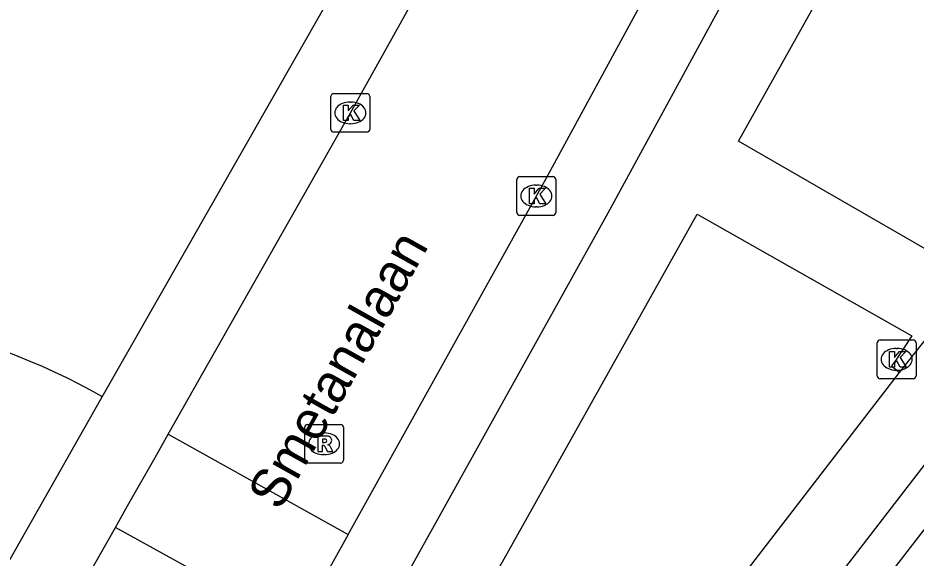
# Model space of a CAD drawing. Extents: x 159040 to 160094, y 381214 to 382518.
# Drawn here: x 159188.7 to 159211.87, y 381534.73 to 381548.68 of the extents above; entities that cross this region are included whole.
import ezdxf

# ---------------------------------------------------------------- set-up
doc = ezdxf.new("R2010")
doc.units = 0
for name, color, linetype in [('IMGEO_Groenvoorziening', 7, 'Continuous'), ('IMGEO_Kolk', 7, 'Continuous'), ('IMGEO_Openbare_ruimte_label', 7, 'Continuous'), ('IMGEO_Pand', 7, 'Continuous'), ('IMGEO_Rijbaan_lokaal_open', 7, 'Continuous'), ('IMGEO_Rioolput', 7, 'Continuous'), ('IMGEO_Voetpad_open', 7, 'Continuous')]:
    doc.layers.add(name, color=color, linetype=linetype)

msp = doc.modelspace()

# ---------------------------------------------------------------- linework, layer by layer
at = {"layer": 'IMGEO_Groenvoorziening'}
msp.add_arc((159182.126, 381523.448), 17.751, 60.4649, 199.9506, dxfattribs=at)
at = {"layer": 'IMGEO_Kolk'}
for p, q in [((159196.775, 381545.799), (159196.775, 381546.651)), ((159196.85, 381546.725), (159197.702, 381546.725)), ((159197.776, 381546.651), (159197.776, 381545.799)), ((159197.263, 381546.505), (159197.288, 381546.505)), ((159197.286, 381545.945), (159197.261, 381545.945)), ((159197.702, 381545.725), (159196.85, 381545.725)), ((159201.574, 381543.652), (159201.574, 381544.504)), ((159201.649, 381544.578), (159202.501, 381544.578)), ((159202.575, 381544.504), (159202.575, 381543.652)), ((159202.062, 381544.358), (159202.087, 381544.358)), ((159202.085, 381543.798), (159202.06, 381543.798)), ((159202.501, 381543.578), (159201.649, 381543.578)), ((159210.945, 381540.36), (159211.797, 381540.36)), ((159210.87, 381539.434), (159210.87, 381540.286)), ((159211.358, 381540.14), (159211.383, 381540.14)), ((159211.871, 381540.286), (159211.871, 381539.434)), ((159211.381, 381539.58), (159211.356, 381539.58)), ((159211.797, 381539.36), (159210.945, 381539.36))]:
    msp.add_line(p, q, dxfattribs=at)
for points in [[(159196.775, 381545.799), (159196.775, 381546.651)], [(159196.85, 381546.725), (159197.702, 381546.725)], [(159197.776, 381546.651), (159197.776, 381545.799)], [(159197.096, 381546.425), (159197.219, 381546.425), (159197.219, 381546.274), (159197.349, 381546.425), (159197.513, 381546.425), (159197.367, 381546.274), (159197.52, 381546.025), (159197.368, 381546.025), (159197.283, 381546.189), (159197.219, 381546.122), (159197.219, 381546.025), (159197.096, 381546.025), (159197.096, 381546.425)], [(159197.702, 381545.725), (159196.85, 381545.725)], [(159201.574, 381543.652), (159201.574, 381544.504)], [(159201.649, 381544.578), (159202.501, 381544.578)], [(159202.575, 381544.504), (159202.575, 381543.652)], [(159201.895, 381544.278), (159202.018, 381544.278), (159202.018, 381544.127), (159202.148, 381544.278), (159202.312, 381544.278), (159202.166, 381544.127), (159202.319, 381543.878), (159202.167, 381543.878), (159202.082, 381544.042), (159202.018, 381543.975), (159202.018, 381543.878), (159201.895, 381543.878), (159201.895, 381544.278)], [(159202.501, 381543.578), (159201.649, 381543.578)], [(159210.945, 381540.36), (159211.797, 381540.36)], [(159210.87, 381539.434), (159210.87, 381540.286)], [(159211.871, 381540.286), (159211.871, 381539.434)], [(159211.191, 381540.06), (159211.314, 381540.06), (159211.314, 381539.909), (159211.444, 381540.06), (159211.608, 381540.06), (159211.462, 381539.909), (159211.615, 381539.66), (159211.463, 381539.66), (159211.378, 381539.824), (159211.314, 381539.757), (159211.314, 381539.66), (159211.191, 381539.66), (159211.191, 381540.06)], [(159211.797, 381539.36), (159210.945, 381539.36)]]:
    msp.add_lwpolyline(points, dxfattribs=at)
for centre, start, end in [((159196.852, 381546.649), 91.552, 178.448), ((159196.852, 381546.649), 91.552, 178.448), ((159197.7, 381546.649), 1.552, 88.448), ((159197.7, 381546.649), 1.552, 88.448), ((159196.852, 381545.801), 181.552, 268.448), ((159196.852, 381545.801), 181.552, 268.448), ((159197.7, 381545.801), 271.552, 358.448), ((159197.7, 381545.801), 271.552, 358.448), ((159201.651, 381544.502), 91.552, 178.448), ((159201.651, 381544.502), 91.552, 178.448), ((159202.499, 381544.502), 1.552, 88.448), ((159202.499, 381544.502), 1.552, 88.448), ((159201.651, 381543.654), 181.552, 268.448), ((159201.651, 381543.654), 181.552, 268.448), ((159202.499, 381543.654), 271.552, 358.448), ((159202.499, 381543.654), 271.552, 358.448), ((159210.947, 381540.284), 91.552, 178.448), ((159210.947, 381540.284), 91.552, 178.448), ((159211.795, 381540.284), 1.552, 88.448), ((159211.795, 381540.284), 1.552, 88.448), ((159210.947, 381539.436), 181.552, 268.448), ((159210.947, 381539.436), 181.552, 268.448), ((159211.795, 381539.436), 271.552, 358.448), ((159211.795, 381539.436), 271.552, 358.448)]:
    msp.add_arc(centre, 0.0765, start, end, dxfattribs=at)
for centre, major_axis, ratio, start_param, end_param in [((159197.262, 381546.225), (-0.387, 0.002), 0.722429, 4.712389, 7.853982), ((159197.287, 381546.225), (-0.39, 0.002), 0.717154, 1.570796, 4.712389), ((159202.061, 381544.078), (-0.387, 0.002), 0.722429, 4.712389, 7.853982), ((159202.086, 381544.078), (-0.39, 0.002), 0.717154, 1.570796, 4.712389), ((159211.357, 381539.86), (-0.387, 0.002), 0.722429, 4.712389, 7.853982), ((159211.382, 381539.86), (-0.39, 0.002), 0.717154, 1.570796, 4.712389)]:
    msp.add_ellipse(centre, major_axis=major_axis, ratio=ratio, start_param=start_param, end_param=end_param, dxfattribs=at)
at = {"layer": 'IMGEO_Pand'}
msp.add_lwpolyline([(159212.574, 381536.106), (159209.143, 381531.656)], dxfattribs=at)
at = {"layer": 'IMGEO_Rijbaan_lokaal_open'}
for points in [[(159197.222, 381535.339), (159202.327, 381544.533), (159207.32, 381553.722), (159210.549, 381559.319)], [(159192.572, 381537.926), (159197.281, 381546.224), (159203.987, 381558.272)], [(159191.214, 381535.521), (159191.522, 381536.074), (159192.27, 381537.381), (159192.572, 381537.926)], [(159192.572, 381537.926), (159197.222, 381535.339)], [(159189.893, 381533.157), (159190.114, 381533.578), (159191.214, 381535.521)], [(159195.889, 381532.938), (159191.214, 381535.521)], [(159197.222, 381535.339), (159195.889, 381532.938)]]:
    msp.add_lwpolyline(points, dxfattribs=at)
at = {"layer": 'IMGEO_Rioolput'}
for p, q in [((159196.097, 381537.252), (159196.097, 381538.104)), ((159196.172, 381538.178), (159197.024, 381538.178)), ((159197.098, 381538.104), (159197.098, 381537.252)), ((159196.585, 381537.958), (159196.61, 381537.958)), ((159196.608, 381537.398), (159196.583, 381537.398)), ((159197.024, 381537.178), (159196.172, 381537.178))]:
    msp.add_line(p, q, dxfattribs=at)
for points in [[(159196.097, 381537.252), (159196.097, 381538.104)], [(159196.172, 381538.178), (159197.024, 381538.178)], [(159197.098, 381538.104), (159197.098, 381537.252)], [(159196.686, 381537.876), (159196.434, 381537.878), (159196.434, 381537.478)], [(159196.612, 381537.797), (159196.558, 381537.797), (159196.558, 381537.716)], [(159196.434, 381537.478), (159196.558, 381537.478), (159196.558, 381537.64), (159196.569, 381537.64)], [(159196.558, 381537.716), (159196.61, 381537.716)], [(159196.616, 381537.611), (159196.687, 381537.478), (159196.827, 381537.478), (159196.762, 381537.604)], [(159197.024, 381537.178), (159196.172, 381537.178)]]:
    msp.add_lwpolyline(points, dxfattribs=at)
for centre, radius, start, end in [((159196.174, 381538.102), 0.0765, 91.552, 178.448), ((159196.174, 381538.102), 0.0765, 91.552, 178.448), ((159197.022, 381538.102), 0.0765, 1.552, 88.448), ((159197.022, 381538.102), 0.0765, 1.552, 88.448), ((159196.618, 381537.701), 0.0964, 77.0061, 93.1865), ((159196.632, 381537.758), 0.0378, 276.6634, 79.6772), ((159196.685, 381537.766), 0.109, 350.3612, 89.416), ((159196.568, 381537.587), 0.0533, 26.0293, 88.6989), ((159196.594, 381537.905), 0.19, 274.7715, 282.9687), ((159196.683, 381537.766), 0.112, 277.5842, 350.9817), ((159196.667, 381537.551), 0.108, 29.5134, 73.7905), ((159196.174, 381537.254), 0.0765, 181.552, 268.448), ((159196.174, 381537.254), 0.0765, 181.552, 268.448), ((159197.022, 381537.254), 0.0765, 271.552, 358.448), ((159197.022, 381537.254), 0.0765, 271.552, 358.448)]:
    msp.add_arc(centre, radius, start, end, dxfattribs=at)
for centre, major_axis, ratio, start_param, end_param in [((159196.584, 381537.678), (-0.387, 0.002), 0.722429, 4.712389, 7.853982), ((159196.609, 381537.678), (-0.39, 0.002), 0.717154, 1.570796, 4.712389)]:
    msp.add_ellipse(centre, major_axis=major_axis, ratio=ratio, start_param=start_param, end_param=end_param, dxfattribs=at)
at = {"layer": 'IMGEO_Voetpad_open'}
for points in [[(159213.388, 381541.973), (159207.287, 381545.497), (159215.578, 381560.327), (159215.764, 381560.612)], [(159212.41, 381558.977), (159212.162, 381558.46), (159208.914, 381552.829), (159203.917, 381543.633), (159194.753, 381527.128), (159186.552, 381512.755), (159185.268, 381510.556)], [(159192.033, 381511.095), (159225.401, 381554.424)], [(159190.876, 381538.892), (159196.616, 381548.975)], [(159201.832, 381527.029), (159198.115, 381529.116), (159206.227, 381543.609), (159211.764, 381540.468), (159211.37, 381539.861), (159211.235, 381539.689), (159211.449, 381539.519)], [(159211.449, 381539.519), (159213.388, 381541.973)], [(159201.832, 381527.029), (159211.449, 381539.519)], [(159173.453, 381507.955), (159176.296, 381513.115), (159179.604, 381518.88), (159180.292, 381520.169), (159180.696, 381520.785), (159188.162, 381534.124), (159190.876, 381538.892)]]:
    msp.add_lwpolyline(points, dxfattribs=at)

# ---------------------------------------------------------------- texts
at = {"layer": 'IMGEO_Openbare_ruimte_label'}
msp.add_text('Smetanalaan', height=1, rotation=60.7172, dxfattribs=at).set_placement((159195.456, 381535.919))

doc.saveas('drawing.dxf')
